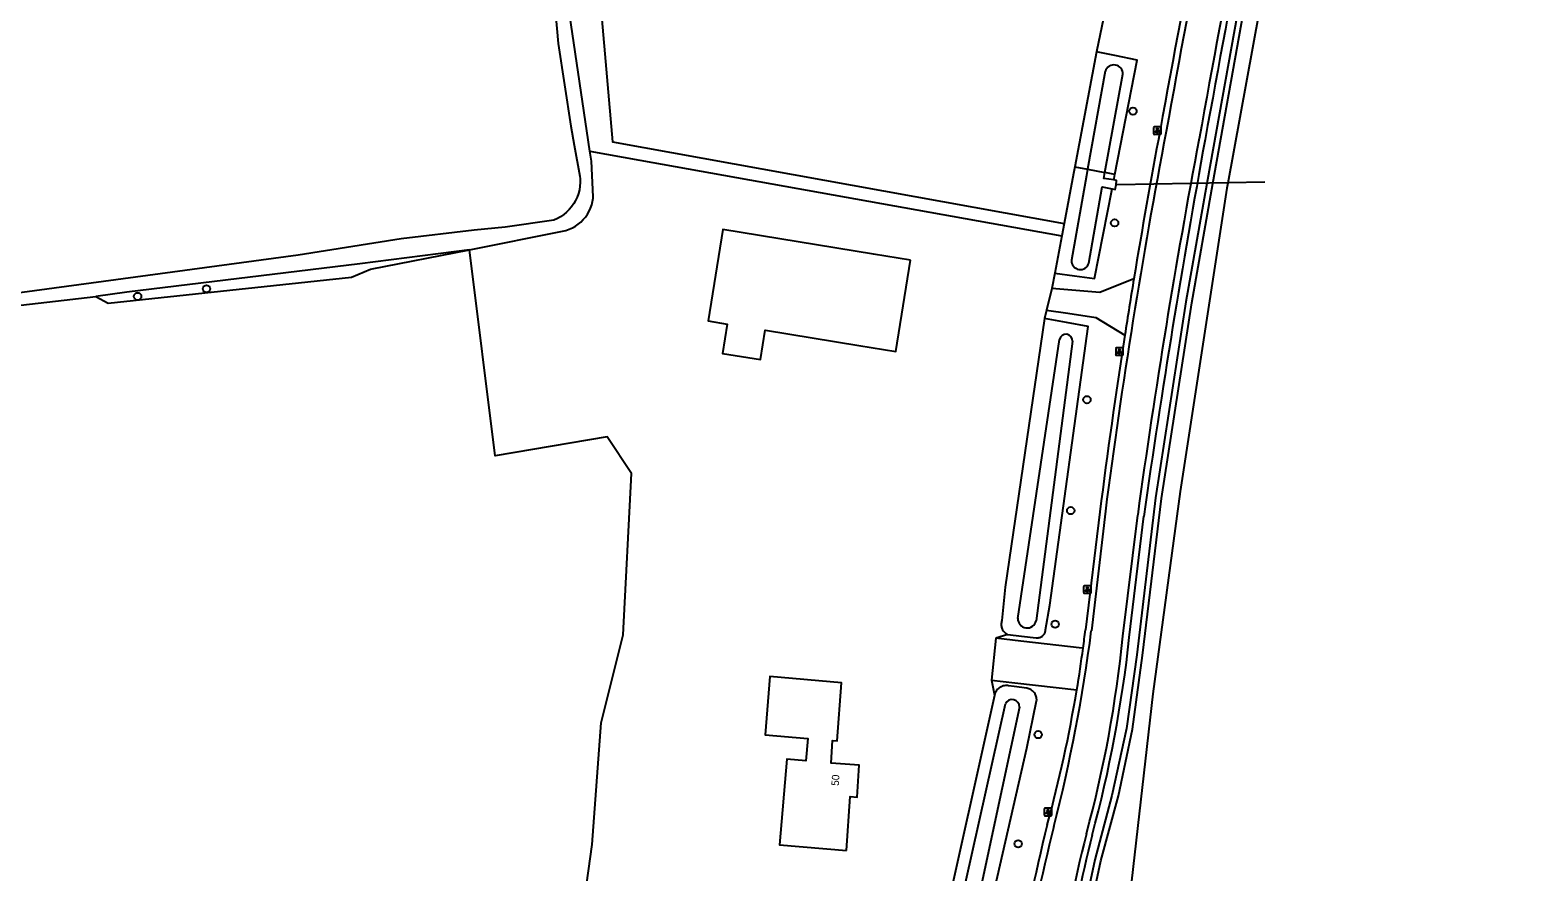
# Model space of a CAD drawing. Extents: x 161389 to 162585, y 388479 to 389761.
# Drawn here: x 162380.1 to 162581.2, y 389135.6 to 389247.8 of the extents above; entities that cross this region are included whole.
import ezdxf

# ---------------------------------------------------------------- set-up
doc = ezdxf.new("R2010")
doc.units = 0
for name, color, linetype in [('IMGEO_Berm_open', 7, 'Continuous'), ('IMGEO_Boom', 7, 'Continuous'), ('IMGEO_Bouwland', 7, 'Continuous'), ('IMGEO_Duiker', 7, 'Continuous'), ('IMGEO_Erf', 7, 'Continuous'), ('IMGEO_Fietspad_gesloten', 7, 'Continuous'), ('IMGEO_Grasland_overig', 7, 'Continuous'), ('IMGEO_Groenvoorziening', 7, 'Continuous'), ('IMGEO_Haag', 7, 'Continuous'), ('IMGEO_Hek', 7, 'Continuous'), ('IMGEO_Lichtpunt', 7, 'Continuous'), ('IMGEO_Oever', 7, 'Continuous'), ('IMGEO_Pand', 7, 'Continuous'), ('IMGEO_Pand_nummerreeks', 7, 'Continuous'), ('IMGEO_Rijbaan_lokaal_open', 7, 'Continuous'), ('IMGEO_Rijbaan_regionaal_gesloten', 7, 'Continuous'), ('IMGEO_Waterloop', 7, 'Continuous')]:
    doc.layers.add(name, color=color, linetype=linetype)

msp = doc.modelspace()

# ---------------------------------------------------------------- linework, layer by layer
at = {"layer": 'IMGEO_Berm_open'}
for points in [[(162522.77, 389183.57), (162520.84, 389167.84)], [(162526.7, 389166.82), (162528.63, 389182.97)]]:
    msp.add_lwpolyline(points, dxfattribs=at)
for centre, radius, start, end in [((166558.63, 388497.78), 4094.64, 168.80107, 169.63564), ((165430.74, 388709.98), 2940.85, 168.58464, 169.75115), ((163383.98, 389073.51), 868.22, 169.3186, 170.64564), ((163865.58, 388991.1), 1350.65, 169.67296, 171.83337), ((163371.45, 389075.44), 855.54, 171.14652, 172.73911), ((162337.16, 389189.91), 185.01, 352.3841, 353.1464), ((162353.56, 389185.73), 174.17, 344.9225, 353.7664), ((162342.8, 389189.17), 179.31, 344.6948, 350.5867), ((162735.65, 389086.74), 226.69, 165.9351, 171.2124), ((162738.94, 389086.46), 223.81, 166.0456, 175.0996)]:
    msp.add_arc(centre, radius, start, end, dxfattribs=at)
at = {"layer": 'IMGEO_Boom'}
for centre in [(162527.19, 389236.99), (162524.74, 389222.09), (162394.43, 389212.3), (162403.61, 389213.31), (162521.05, 389198.52), (162518.88, 389183.72), (162516.81, 389168.58), (162514.53, 389153.85), (162511.88, 389139.28)]:
    msp.add_circle(centre, 0.489, dxfattribs=at)
at = {"layer": 'IMGEO_Bouwland'}
for points in [[(162523.68, 389251.54), (162522.32, 389244.9)], [(162522.32, 389244.9), (162519.43, 389229.57)], [(162519.43, 389229.57), (162519.26, 389228.69), (162518.01, 389222.01)], [(162452.14, 389118.14), (162455.04, 389139.22), (162456.26, 389155.42), (162459.17, 389167.14), (162460.31, 389188.68), (162457.04, 389193.56), (162442.11, 389191.05), (162438.69, 389218.52)]]:
    msp.add_lwpolyline(points, dxfattribs=at)
at = {"layer": 'IMGEO_Duiker'}
msp.add_lwpolyline([(162525.04, 389227.23), (162544.78, 389227.55)], dxfattribs=at)
at = {"layer": 'IMGEO_Erf'}
for points in [[(162517.7, 389220.36), (162516.77, 389215.38)], [(162515.4, 389209.36), (162510.13, 389173.5), (162509.71, 389169.06), (162509.67, 389168.93), (162509.64, 389168.81), (162509.62, 389168.68), (162509.61, 389168.55), (162509.61, 389168.42), (162509.63, 389168.29), (162509.66, 389168.17), (162509.69, 389168.04), (162509.74, 389167.92), (162509.8, 389167.81), (162509.87, 389167.7), (162509.95, 389167.6), (162510.04, 389167.51), (162510.14, 389167.42), (162510.24, 389167.34), (162510.35, 389167.27), (162510.46, 389167.22), (162510.49, 389167.21)], [(162508.73, 389159.13), (162508.71, 389159.07), (162501.65, 389127.29), (162464.29, 389120.39)]]:
    msp.add_lwpolyline(points, dxfattribs=at)
at = {"layer": 'IMGEO_Fietspad_gesloten'}
for points in [[(162523.51, 389183.65), (162521.64, 389167.68)], [(162525.85, 389166.98), (162527.82, 389183.14)]]:
    msp.add_lwpolyline(points, dxfattribs=at)
for centre, radius, start, end in [((165549.5, 388690.44), 3066.49, 168.66946, 169.78423), ((165801.81, 388642.75), 3318.76, 168.71278, 169.74959), ((163380.67, 389072.21), 864.38, 169.19171, 172.59244), ((163529.83, 389045.24), 1011.46, 169.28293, 172.16365), ((162300.78, 389196.46), 222.72, 345.7416, 352.5741), ((162361.08, 389183.83), 165.63, 344.8832, 354.1641), ((162731.04, 389086.79), 221.29, 165.6569, 176.2937), ((162729.97, 389087.83), 215.56, 165.8212, 176.6524)]:
    msp.add_arc(centre, radius, start, end, dxfattribs=at)
at = {"layer": 'IMGEO_Grasland_overig'}
for points in [[(162291.12, 389378.53), (162299.26, 389341.62), (162311.5, 389305.21), (162312.34, 389304.54), (162314.69, 389304.21), (162318.3, 389303.87), (162322.83, 389303.62), (162328.2, 389303.62), (162343.55, 389303.96), (162365.69, 389304.53), (162378.86, 389305.21), (162381.46, 389305.34), (162386.58, 389305.3), (162392.87, 389304.96), (162400.44, 389304.98), (162407.4, 389305.15), (162413.86, 389305.32), (162420.57, 389304.98), (162428.12, 389304.98), (162438.44, 389304.9), (162451.55, 389304.33), (162457.77, 389232.9), (162518.01, 389222.01)], [(162454.75, 389231.66), (162461.43, 389230.46), (162517.7, 389220.36)], [(162518.01, 389222.01), (162517.7, 389220.36)], [(162388.85, 389212.27), (162390.49, 389211.37), (162422.97, 389214.86), (162425.48, 389215.91), (162438.69, 389218.52)]]:
    msp.add_lwpolyline(points, dxfattribs=at)
at = {"layer": 'IMGEO_Groenvoorziening'}
for points in [[(162524.77, 389228.54), (162527.74, 389243.79), (162524.75, 389244.4), (162522.32, 389244.9)], [(162524.63, 389227.82), (162524.66, 389228.01), (162524.77, 389228.54)], [(162516.77, 389215.38), (162519.37, 389215.03), (162522.07, 389214.66), (162524.36, 389226.43), (162524.4, 389226.64)], [(162516.77, 389215.38), (162516.35, 389213.36)], [(162510.49, 389167.21), (162512.33, 389166.99), (162514.26, 389166.78), (162514.36, 389166.77), (162514.46, 389166.77), (162514.55, 389166.77), (162514.65, 389166.79), (162514.75, 389166.81), (162514.85, 389166.85), (162514.94, 389166.89), (162515.02, 389166.94), (162515.1, 389167), (162515.18, 389167.06), (162515.25, 389167.14), (162515.31, 389167.21), (162515.37, 389167.29), (162515.42, 389167.38), (162515.46, 389167.47), (162515.49, 389167.57), (162515.52, 389167.66), (162515.53, 389167.76), (162515.54, 389167.83), (162516.09, 389171.11), (162521.21, 389208.29), (162518.31, 389208.83), (162515.4, 389209.36)], [(162515.66, 389210.47), (162515.4, 389209.36)], [(162510.49, 389167.21), (162508.89, 389166.7)], [(162507.36, 389127.14), (162513.03, 389152.06), (162514.34, 389158.38), (162514.35, 389158.51), (162514.34, 389158.65), (162514.32, 389158.79), (162514.29, 389158.92), (162514.25, 389159.05), (162514.2, 389159.17), (162514.13, 389159.3), (162514.06, 389159.41), (162513.97, 389159.52), (162513.88, 389159.62), (162513.77, 389159.71), (162513.66, 389159.79), (162513.55, 389159.86), (162513.42, 389159.92), (162513.29, 389159.97), (162513.16, 389160.01), (162513.04, 389160.03), (162511.35, 389160.28), (162510.6, 389160.38), (162510.46, 389160.4), (162510.31, 389160.41), (162510.17, 389160.4), (162510.02, 389160.38), (162509.88, 389160.35), (162509.74, 389160.3), (162509.61, 389160.24), (162509.48, 389160.17), (162509.36, 389160.09), (162509.24, 389160), (162509.14, 389159.9), (162509.04, 389159.79), (162508.95, 389159.67), (162508.88, 389159.54), (162508.82, 389159.41), (162508.76, 389159.27), (162508.73, 389159.13)], [(162508.3, 389161.12), (162508.73, 389159.13)]]:
    msp.add_lwpolyline(points, dxfattribs=at)
at = {"layer": 'IMGEO_Haag'}
for points in [[(162576.4, 389611.95), (162580.02, 389588.59), (162581.19, 389573.81), (162581.11, 389548.91), (162580.88, 389537.22), (162580.28, 389524.99), (162575.53, 389457.9), (162574.18, 389443.82), (162572.86, 389427.68), (162570.7, 389413.37), (162566.1, 389385.68), (162560.93, 389354.66), (162556.8, 389331.01), (162550.72, 389299.24), (162545.52, 389273.57), (162541.11, 389250.07), (162537.05, 389227.35), (162534.23, 389211.56), (162530.19, 389185.45), (162527.69, 389164.49), (162526.33, 389154.68), (162524.35, 389145.75), (162522.08, 389137.16), (162518.58, 389120.76)], [(162517.09, 389105.51), (162517.41, 389109.82), (162519.37, 389120.59), (162522.92, 389137.04), (162525.27, 389145.69), (162527.13, 389154.56), (162528.48, 389164.39), (162530.98, 389185.34), (162535.02, 389211.43), (162537.86, 389227.36), (162541.89, 389249.93), (162546.3, 389273.41), (162551.5, 389299.09), (162557.59, 389330.87), (162561.72, 389354.52), (162566.89, 389385.56)]]:
    msp.add_lwpolyline(points, dxfattribs=at)
at = {"layer": 'IMGEO_Hek'}
msp.add_lwpolyline([(162454.75, 389231.66), (162461.43, 389230.46)], dxfattribs=at)
at = {"layer": 'IMGEO_Lichtpunt'}
for p, q in [((162529.94, 389234.81), (162529.94, 389234)), ((162529.94, 389234.81), (162529.94, 389234)), ((162530.84, 389234.9), (162530.04, 389234.9)), ((162530.84, 389234.9), (162530.04, 389234.9)), ((162530.94, 389234), (162530.94, 389234.81)), ((162530.94, 389234), (162530.94, 389234.81)), ((162530.04, 389233.91), (162530.84, 389233.91)), ((162530.04, 389233.91), (162530.84, 389233.91)), ((162524.88, 389205.34), (162524.88, 389204.53)), ((162524.88, 389205.34), (162524.88, 389204.53)), ((162525.78, 389205.44), (162524.97, 389205.44)), ((162525.78, 389205.44), (162524.97, 389205.44)), ((162525.87, 389204.53), (162525.87, 389205.34)), ((162525.87, 389204.53), (162525.87, 389205.34)), ((162524.97, 389204.44), (162525.78, 389204.44)), ((162524.97, 389204.44), (162525.78, 389204.44)), ((162520.61, 389173.6), (162520.61, 389172.79)), ((162520.61, 389173.6), (162520.61, 389172.79)), ((162521.52, 389173.7), (162520.71, 389173.7)), ((162521.52, 389173.7), (162520.71, 389173.7)), ((162520.71, 389172.7), (162521.52, 389172.7)), ((162520.71, 389172.7), (162521.52, 389172.7)), ((162521.61, 389172.79), (162521.61, 389173.6)), ((162521.61, 389172.79), (162521.61, 389173.6)), ((162515.36, 389143.95), (162515.36, 389143.14)), ((162515.36, 389143.95), (162515.36, 389143.14)), ((162516.26, 389144.04), (162515.46, 389144.04)), ((162516.26, 389144.04), (162515.46, 389144.04)), ((162515.46, 389143.04), (162516.26, 389143.04)), ((162515.46, 389143.04), (162516.26, 389143.04)), ((162516.36, 389143.14), (162516.36, 389143.95)), ((162516.36, 389143.14), (162516.36, 389143.95))]:
    msp.add_line(p, q, dxfattribs=at)
for points in [[(162530.32, 389234.47), (162530.35, 389234.45), (162530.17, 389234.18), (162530.13, 389234.21), (162530.32, 389234.47)], [(162530.42, 389234.43), (162530.47, 389234.43), (162530.47, 389234.1), (162530.42, 389234.1), (162530.42, 389234.43)], [(162530.53, 389234.45), (162530.57, 389234.47), (162530.75, 389234.21), (162530.71, 389234.18), (162530.53, 389234.45)], [(162525.25, 389205), (162525.29, 389204.98), (162525.1, 389204.71), (162525.06, 389204.74), (162525.25, 389205)], [(162525.35, 389204.96), (162525.4, 389204.96), (162525.4, 389204.63), (162525.35, 389204.63), (162525.35, 389204.96)], [(162525.46, 389204.98), (162525.5, 389205), (162525.69, 389204.74), (162525.65, 389204.71), (162525.46, 389204.98)], [(162520.99, 389173.26), (162521.03, 389173.24), (162520.84, 389172.97), (162520.8, 389173), (162520.99, 389173.26)], [(162521.09, 389173.22), (162521.14, 389173.22), (162521.14, 389172.89), (162521.09, 389172.89), (162521.09, 389173.22)], [(162521.2, 389173.24), (162521.24, 389173.26), (162521.42, 389173), (162521.39, 389172.97), (162521.2, 389173.24)], [(162515.74, 389143.61), (162515.77, 389143.58), (162515.59, 389143.32), (162515.55, 389143.35), (162515.74, 389143.61)], [(162515.84, 389143.56), (162515.89, 389143.56), (162515.89, 389143.24), (162515.84, 389143.24), (162515.84, 389143.56)], [(162515.95, 389143.58), (162515.99, 389143.61), (162516.17, 389143.35), (162516.13, 389143.32), (162515.95, 389143.58)]]:
    msp.add_lwpolyline(points, dxfattribs=at)
for centre in [(162530.44, 389234.61), (162525.38, 389205.14), (162521.11, 389173.4), (162515.86, 389143.74)]:
    msp.add_circle(centre, 0.0994, dxfattribs=at)
for centre, start, end in [((162530.04, 389234.81), 90, 180), ((162530.04, 389234.81), 90, 180), ((162530.84, 389234.81), 0, 90), ((162530.84, 389234.81), 0, 90), ((162530.04, 389234), 180, 270), ((162530.04, 389234), 180, 270), ((162530.84, 389234), 270, 0), ((162530.84, 389234), 270, 360), ((162524.97, 389205.34), 90, 180), ((162524.97, 389205.34), 90, 180), ((162525.78, 389205.34), 0, 90), ((162525.78, 389205.34), 0, 90), ((162524.97, 389204.53), 180, 270), ((162524.97, 389204.53), 180, 270), ((162525.78, 389204.53), 270, 0), ((162525.78, 389204.53), 270, 360), ((162520.71, 389173.6), 90, 180), ((162520.71, 389173.6), 90, 180), ((162520.71, 389172.79), 180, 270), ((162520.71, 389172.79), 180, 270), ((162521.52, 389173.6), 0, 90), ((162521.52, 389173.6), 0, 90), ((162521.52, 389172.79), 270, 0), ((162521.52, 389172.79), 270, 360), ((162515.46, 389143.95), 90, 180), ((162515.46, 389143.95), 90, 180), ((162515.46, 389143.14), 180, 270), ((162515.46, 389143.14), 180, 270), ((162516.26, 389143.95), 0, 90), ((162516.26, 389143.95), 0, 90), ((162516.26, 389143.14), 270, 0), ((162516.26, 389143.14), 270, 360)]:
    msp.add_arc(centre, 0.0946, start, end, dxfattribs=at)
at = {"layer": 'IMGEO_Oever'}
for points in [[(162519.43, 389229.57), (162521.14, 389229.24)], [(162524.77, 389228.54), (162523.43, 389228.8)]]:
    msp.add_lwpolyline(points, dxfattribs=at)
at = {"layer": 'IMGEO_Pand'}
for points in [[(162497.51, 389217.14), (162492.58, 389217.94), (162472.48, 389221.22), (162470.53, 389209.03), (162473.08, 389208.61), (162472.45, 389204.69), (162477.51, 389203.86), (162478.14, 389207.79), (162478.19, 389207.78), (162490.62, 389205.75), (162495.55, 389204.94), (162497.51, 389217.14)], [(162488.99, 389138.39), (162489.48, 389145.58), (162490.38, 389145.52), (162490.66, 389149.8), (162486.92, 389150.06), (162487.13, 389153.06), (162487.73, 389153.02), (162488.32, 389160.78), (162478.77, 389161.59), (162478.11, 389153.82), (162483.8, 389153.34), (162483.55, 389150.36), (162481.01, 389150.57), (162480.05, 389139.14), (162488.99, 389138.39)]]:
    msp.add_lwpolyline(points, dxfattribs=at)
at = {"layer": 'IMGEO_Rijbaan_lokaal_open'}
for points in [[(162527.3, 389214.64), (162522.77, 389212.8), (162519.05, 389213.13), (162516.35, 389213.36)], [(162516.35, 389213.36), (162515.66, 389210.47)], [(162515.66, 389210.47), (162518.52, 389210.04), (162522.25, 389209.48), (162526.1, 389207.11)], [(162508.89, 389166.7), (162508.3, 389161.12)], [(162520.53, 389165.39), (162520.41, 389165.4), (162512.24, 389166.33), (162508.89, 389166.7)], [(162508.3, 389161.12), (162511.42, 389160.77), (162519.7, 389159.84)]]:
    msp.add_lwpolyline(points, dxfattribs=at)
for centre, radius, start, end in [((163357.31, 389077.87), 841.2, 170.64276, 171.16184), ((162340.51, 389189.55), 181.64, 350.5844, 352.3561)]:
    msp.add_arc(centre, radius, start, end, dxfattribs=at)
at = {"layer": 'IMGEO_Rijbaan_regionaal_gesloten'}
msp.add_lwpolyline([(162568.52, 389385.32), (162566.28, 389369.56), (162559.5, 389330.64), (162553.24, 389299.28), (162543.99, 389250), (162539.82, 389227.39), (162539.7, 389226.74), (162533.46, 389186.29), (162529.83, 389159.28), (162527.01, 389134.31), (162524.67, 389105.18)], dxfattribs=at)
at = {"layer": 'IMGEO_Waterloop'}
for points in [[(162450.17, 389250), (162450.51, 389246.03), (162452.19, 389235.01), (162452.66, 389232.48), (162453.43, 389228.33), (162453.46, 389227.98), (162453.47, 389227.48), (162453.43, 389226.99), (162453.35, 389226.49), (162453.23, 389226.01), (162453.06, 389225.54), (162452.85, 389225.09), (162452.6, 389224.66), (162452.32, 389224.25), (162451.99, 389223.87), (162451.64, 389223.51), (162451.26, 389223.2), (162450.85, 389222.91), (162450.41, 389222.67), (162449.96, 389222.46), (162443.45, 389221.54), (162439.3, 389221.11), (162429.58, 389219.97), (162415.85, 389217.78), (162377.38, 389212.6)], [(162454.75, 389231.66), (162452.04, 389250)], [(162523.5, 389242.32), (162521.14, 389229.24)], [(162523.43, 389228.8), (162525.84, 389241.91)], [(162438.69, 389218.52), (162451.11, 389220.98), (162451.55, 389221.09), (162451.99, 389221.24), (162452.41, 389221.43), (162452.81, 389221.65), (162453.18, 389221.91), (162453.54, 389222.21), (162453.86, 389222.53), (162454.16, 389222.88), (162454.42, 389223.26), (162454.65, 389223.65), (162454.84, 389224.07), (162455, 389224.5), (162455.11, 389224.95), (162455.19, 389225.4), (162455.21, 389225.57), (162454.95, 389230.31), (162454.75, 389231.66)], [(162521.14, 389229.24), (162520.99, 389228.41), (162519, 389217.13)], [(162521.14, 389229.24), (162523.43, 389228.8)], [(162524.63, 389227.82), (162523.28, 389228.03), (162523.43, 389228.8)], [(162521.31, 389216.74), (162523.08, 389226.89), (162524.4, 389226.64)], [(162524.4, 389226.64), (162524.81, 389226.56), (162524.96, 389227.16), (162525, 389227.76), (162524.63, 389227.82)], [(162438.69, 389218.52), (162424.06, 389216.65), (162392.98, 389212.86), (162388.85, 389212.27)], [(162362.01, 389209.81), (162362.09, 389209.49), (162362.25, 389209.27), (162362.66, 389209.24), (162388.85, 389212.27)], [(162511.83, 389169.36), (162517.39, 389206.56)], [(162519.12, 389206.32), (162514.28, 389169.04)], [(162465.56, 389119.47), (162502.48, 389125.91), (162502.94, 389126.12), (162503.14, 389126.51), (162510.18, 389157.95)], [(162512.05, 389157.52), (162509.73, 389146.76), (162505.11, 389125.18), (162504.78, 389124.79), (162504.18, 389124.6), (162488.97, 389122.14), (162465.85, 389118.02), (162465.56, 389119.47)]]:
    msp.add_lwpolyline(points, dxfattribs=at)
for centre, radius, start, end in [((162524.65, 389241.96), 1.2, 357.2372, 162.8474), ((162520.17, 389217.04), 1.17, 175.6482, 345.1451), ((162518.24, 389206.38), 0.875, 355.8359, 168.0896), ((162513.07, 389169.32), 1.24, 177.9953, 346.9475), ((162511.07, 389157.56), 0.976, 357.8213, 156.2073)]:
    msp.add_arc(centre, radius, start, end, dxfattribs=at)

# ---------------------------------------------------------------- texts
at = {"layer": 'IMGEO_Pand_nummerreeks'}
msp.add_text('50', height=1, rotation=86.257, dxfattribs=at).set_placement((162487.95, 389147))

doc.saveas('drawing.dxf')
